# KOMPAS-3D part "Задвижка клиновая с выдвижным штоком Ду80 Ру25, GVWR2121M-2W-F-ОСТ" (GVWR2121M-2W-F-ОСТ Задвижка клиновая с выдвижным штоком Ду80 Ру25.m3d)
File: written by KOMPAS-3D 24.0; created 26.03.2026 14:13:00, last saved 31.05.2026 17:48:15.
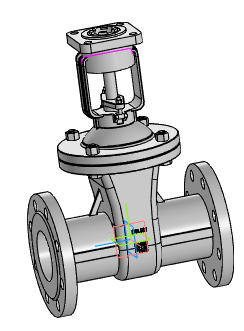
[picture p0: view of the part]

Document properties: Автор: R2D2; Полное имя файла: E:\Работа\Зайцев\GVWR2121M-2W-F-ОСТ Задвижка клиновая 30с964нж DN.ru Ду50-300 Ру25\исходные материалы\DN80\GVWR2121M-2W-F-ОСТ Задвижка клиновая с выдвижным штоком Ду80 Ру25.m3d

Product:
- Component [detail]: AS 1110 - M12 x 45  | qty 4  | pos. 2  | Комментарий: Болты и винты   шестигранные точные   метрические ISO; Автор: R2D2; additional columns: Сталь, мягкая; source file: AS 1110 - M12 x 45 AS 1110 - M12 x 45.m3d
- Component [detail]: ANSI B18.2.4.2M - M12x1,75 - 18  | designation ANSI B18.2.4.2M - M12x1,75  | qty 4  | pos. 3  | Комментарий: Типы метрических   шестигранных гаек   2; Автор: R2D2; additional columns: Сталь, мягкая; source file: ANSI B18.2.4.2M - M12x1,75 ANSI B18.2.4.2M - M12x1,75 - 18.m3d
- Component [detail]: ANSI B18.2.4.2M - M5x0,8 - 8  | designation ANSI B18.2.4.2M - M5x0,8  | qty 2  | pos. 4  | Комментарий: Типы метрических   шестигранных гаек   2; Автор: R2D2; additional columns: Сталь, мягкая; source file: ANSI B18.2.4.2M - M5x0,8 ANSI B18.2.4.2M - M5x0,8 - 8.m3d
- Component [detail]: Деталь1  | qty 1  | pos. 5  | additional columns: Типовые; source file: 2.m3d
- Component [detail]: Фланец  | qty 2  | pos. 5  | Автор: R2D2; additional columns: Типовые; source file: Фланец DN80 PN25 b22.m3d
- Component [assembly]: DN50_3D_STEP  | designation Сборка  | qty 1  | pos. 6  | Масса: 2.725126; Автор: R2D2; source file: Фланец А.a3d
- Part/product: Задвижка клиновая с выдвижным штоком Ду80 Ру25  | designation GVWR2121M-2W-F-ОСТ
    Масса: 24
    Раздел спецификации: Прочие изделия
    Примечание: D040-08603

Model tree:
1. Массив по концентрической сетке:1  (labels: Грань.Твердое тело1)  (4 pattern instances)
     Шаг 2 = 360
2. Массив по концентрической сетке:2  (labels: Грань.Твердое тело1)  (2 pattern instances)
     Шаг 2 = 360
3. Элемент выдавливания:3  (with: Грань.Элемент выдавливания:2, Грань.Элемент вращения:1)
     Расстояние 1 = 42.7058
4. Элемент выдавливания:4  (with: Грань.Элемент выдавливания:3, Грань.Элемент вращения:1)
     Расстояние 1 = 37.7507
5. Элемент выдавливания:5  (with: Грань.Элемент выдавливания:3)
     Расстояние 1 = 10
6. Эскиз:2  (with: Вершина.Элемент выдавливания:5, Ребро.Элемент выдавливания:3)
7. Элемент по траектории:1  (with: Грань.Элемент выдавливания:5)
     Толщина стенки 1 = 1; Длина траектории = 97.708
8. Эскиз:3  (with: Ребро.Элемент выдавливания:4, Ребро.Элемент выдавливания:3)
9. Элемент вращения:1
     Угол 1 = 360
10. Фаска:1  (with: Ребро.Элемент вращения:1)
     Угол = 45; Длина 1 = 3; Длина 2 = 3
11. Эскиз:4
12. Элемент выдавливания:7  (with: Грань.Элемент выдавливания:3, Грань.Элемент вращения:1, Грань.Операция без истории:2, Грань.Элемент выдавливания:4)  (labels: Грань.Твердое тело1; Грань.Solid1; Solid1; Твердое тело1)
     Расстояние 1 = 61; Смещение 1 = 1; Расстояние = -140; Ориентация = 2; Расстояние = -335

Expressions: 135+6
Referenced files in E:\Работа\Зайцев\GVWR2121M-2W-F-ОСТ Задвижка клиновая 30с964нж DN.ru Ду50-300 Ру25\исходные материалы\DN80\: AS 1110 - M12 x 45 AS 1110 - M12 x 45.m3d, ANSI B18.2.4.2M - M12x1,75 ANSI B18.2.4.2M - M12x1,75 - 18.m3d, ANSI B18.2.4.2M - M5x0,8 ANSI B18.2.4.2M - M5x0,8 - 8.m3d, 2.m3d, Фланец А.a3d, Фланец DN80 PN25 b22.m3d
Referenced files in E:\Работа\Зайцев\GVWR3131M-2W-F-S Задвижка клиновая с выдвижным штоком DN.ru Ду50-200 Ру63\DN80\исходные материалы\: ANSI B18.2.4.2M - M12x1,75 ANSI B18.2.4.2M - M12x1,75 - 18.m3d, AS 1110 - M12 x 45 AS 1110 - M12 x 45.m3d, ANSI B18.2.4.2M - M5x0,8 ANSI B18.2.4.2M - M5x0,8 - 8.m3d
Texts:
  GVWR2121M-2W-F-ОСТ
  DN80
  GOST 26.020 Pr3
  PN25
  AS 1110 - M12 x 45 AS 1110 - M12 x 45 (1)
  ANSI B18.2.4.2M - M12x1,75 ANSI B18.2.4.2M - M12x1,75 - 18 (1)
  ANSI B18.2.4.2M - M5x0,8 ANSI B18.2.4.2M - M5x0,8 - 8 (1)
  Деталь1 Деталь1
  Фланец (1)
  Фланец (2)
  ANSI B18.2.4.2M - M12x1,75 ANSI B18.2.4.2M - M12x1,75 - 18 (2)
  AS 1110 - M12 x 45 AS 1110 - M12 x 45 (2)
  ANSI B18.2.4.2M - M12x1,75 ANSI B18.2.4.2M - M12x1,75 - 18 (3)
  AS 1110 - M12 x 45 AS 1110 - M12 x 45 (3)
  ANSI B18.2.4.2M - M12x1,75 ANSI B18.2.4.2M - M12x1,75 - 18 (4)
  AS 1110 - M12 x 45 AS 1110 - M12 x 45 (4)
  ANSI B18.2.4.2M - M5x0,8 ANSI B18.2.4.2M - M5x0,8 - 8 (2)
  Сборка DN50_3D_STEP
  Ось Y.Начало координат
  Ось Z.Начало координат
  Плоскость ZX.Начало координат
  Плоскость XY.Начало координат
